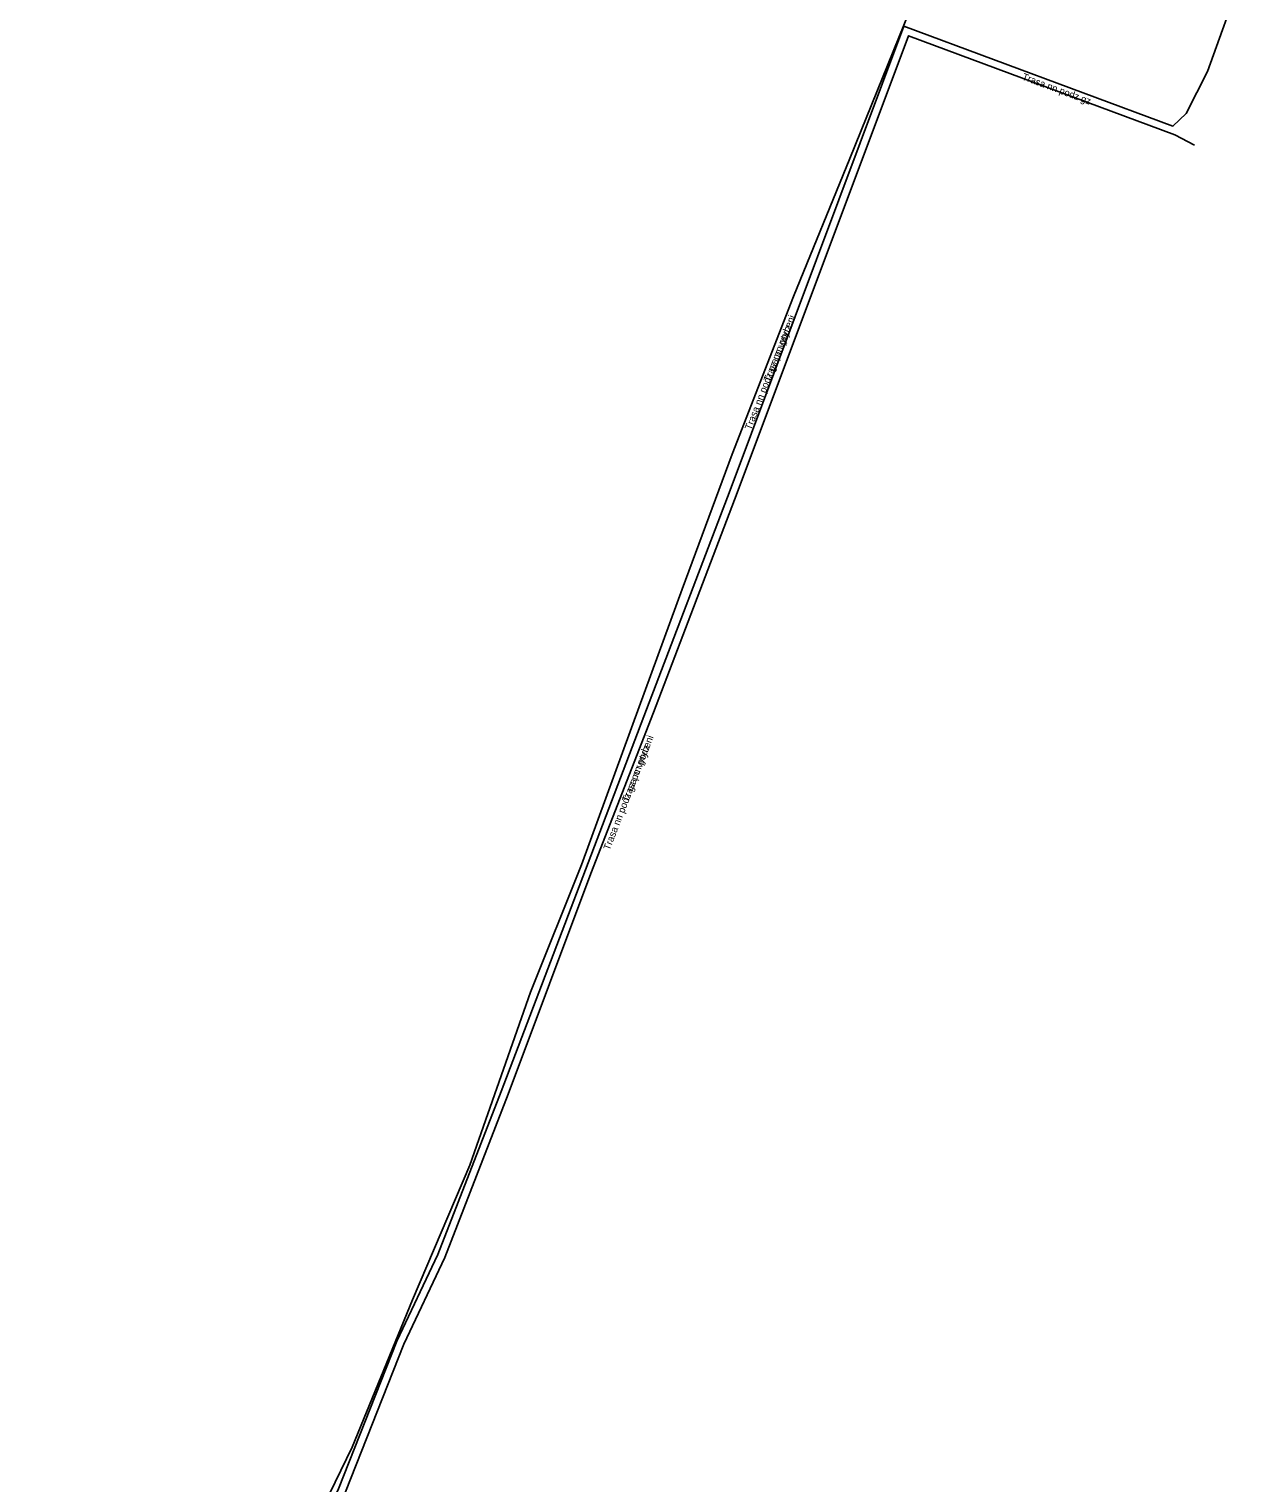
# Model space of a CAD drawing. Extents: x -528168 to -527720, y -1080003 to -1079672.
# Drawn here: x -527834.8 to -527748.5, y -1079897 to -1079793.4 of the extents above; entities that cross this region are included whole.
import ezdxf

# ---------------------------------------------------------------- set-up
doc = ezdxf.new("R2010")
doc.units = 0
doc.layers.add('Popiskový text - Ostatní atributy Trasy', color=7, linetype='Continuous')
doc.layers.add('Spojnice NN', color=7, linetype='Continuous')

msp = doc.modelspace()

# ---------------------------------------------------------------- linework, layer by layer
at = {"layer": 'Spojnice NN'}
for points in [[(-527834.85, -1079903.58), (-527819.81, -1079907.25), (-527814.79, -1079901.47), (-527812.8, -1079897.42), (-527808.66, -1079886.9), (-527805.73, -1079880.72), (-527801.23, -1079869.11), (-527790.88, -1079841.9), (-527784.91, -1079826.27), (-527772.54, -1079793.21), (-527753.38, -1079800.34), (-527752.44, -1079799.43), (-527750.93, -1079796.43), (-527748.47, -1079789.63)], [(-527771.74, -1079791.12), (-527776.4, -1079802.63), (-527780.4, -1079812.47), (-527784.78, -1079823.7), (-527788.33, -1079833.32), (-527791.41, -1079841.7), (-527795.5, -1079852.97), (-527799.14, -1079862.03), (-527803.45, -1079874.36), (-527807.54, -1079883.96), (-527811.84, -1079894.44), (-527814.69, -1079900.32)], [(-527771.74, -1079791.12), (-527776.4, -1079802.63), (-527780.4, -1079812.47), (-527784.78, -1079823.7), (-527788.33, -1079833.32), (-527791.41, -1079841.7), (-527795.5, -1079852.97), (-527799.14, -1079862.03), (-527803.45, -1079874.36), (-527807.54, -1079883.96), (-527811.84, -1079894.44), (-527814.69, -1079900.32)], [(-527751.84, -1079801.69), (-527753.24, -1079800.96), (-527772.22, -1079793.89), (-527784.41, -1079826.45), (-527790.38, -1079842.1), (-527794.83, -1079853.58), (-527800.73, -1079869.3), (-527805.23, -1079880.94), (-527808.17, -1079887.12), (-527812.31, -1079897.64), (-527814.34, -1079901.77), (-527819.63, -1079907.85), (-527827.33, -1079905.97)], [(-527751.84, -1079801.69), (-527753.24, -1079800.96), (-527772.22, -1079793.89), (-527784.41, -1079826.45), (-527790.38, -1079842.1), (-527794.83, -1079853.58), (-527800.73, -1079869.3), (-527805.23, -1079880.94), (-527808.17, -1079887.12), (-527812.31, -1079897.64), (-527814.34, -1079901.77), (-527819.63, -1079907.85), (-527827.33, -1079905.97)]]:
    msp.add_lwpolyline(points, dxfattribs=at)

# ---------------------------------------------------------------- texts
at = {"layer": 'Popiskový text - Ostatní atributy Trasy'}
for s, rotation, p in [('Trasa nn podz gz', 339.5797, (-527764.17, -1079797.01)), ('Trasa nn podz gz po vytyceni', 68.7057, (-527783.43, -1079822.02)), ('Trasa nn podz', 68.7057, (-527782.09, -1079818.59)), ('Trasa nn podz gz po vytyceni', 68.8273, (-527793.5, -1079851.96)), ('Trasa nn podz', 68.8273, (-527792.17, -1079848.52))]:
    msp.add_text(s, height=0.5, rotation=rotation, dxfattribs=at).set_placement(p)

doc.saveas('drawing.dxf')
